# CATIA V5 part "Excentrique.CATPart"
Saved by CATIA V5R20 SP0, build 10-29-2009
Part number: Excentrique
Publications: "Plan.1", "Arête"
Bounding box of the stored display mesh (mm): x -10 to 10, y 114.981 to 189.981, z 26.94 to 101.92
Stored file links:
  C:\Users\thinkmotion1\Desktop\Khaled_IAO_Pack2\IAO_2010_1412_jclement\Non_Optimise\Excentrique.CATPart
  C:\Users\thinkmotion1\Desktop\Khaled_IAO_Pack2\IAO_2010_1412_jclement\Non_Optimise\Synthese IAO_2.CATProduct
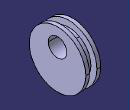
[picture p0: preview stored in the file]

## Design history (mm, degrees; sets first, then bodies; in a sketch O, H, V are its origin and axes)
Set1
  DatumCurve1 to DatumCurve3: linked copy from another document
Set2
  Plane1: type Offset, RefPlane zx-plane, Offset 152.5
Body1 (main body)
  Sketch1 on yz-plane, origin (0, 0, 0), H (0, 1, 0), V (0, 0, 1)
    circle A1 centre (152.4813, 64.4302) radius 37.5
    point P1 (152.4813, 64.4302)
    reference projected arc E1 centre (152.4813, 64.4302) radius 37.5 from (184.557, 83.8568) to (181.554, 88.1161) ccw from edge of DatumCurve1
    circle A2 centre (152.4813, 78.4302) radius 12.2498
    point P2 (152.4813, 78.4302)
    radius A2 = 12.2498
    distance P2 P1 = 14
    distance P2 P1 H = 0
    coincidence: E1 A1
  Pad1: profile Sketch1, direction (1, 0, 0), length 10, mirrored extent
  Sketch2 on Plane1, origin (0, 152.5, 0), H (-1, 0, 0), V (0, 0, 1)
    axis line L1 (-21.2821, 64.4302) -> (42.9523, 64.4302)
    reference projected line E1 through (0, 64.4302) direction (-1, 0) from axis of face of Pad1 from Sketch1.A1
    line L2 (-5, 102.0302) -> (5, 102.0302)
    line L3 (5, 102.0302) -> (5, 93.8302)
    line L4 (5, 93.8302) -> (-5, 93.8302)
    line L5 (-5, 93.8302) -> (-5, 102.0302)
    reference projected line E2 (-5, 83.8359) -> (-5, 89.8146) from edge of DatumCurve3
    length L2 = 10
    length L3 = 8.2
    distance L2 L1 = 37.6
    horizontal: L1 H, L2 H, L4 H
    coincidence: L1 E1, E2 L5
    vertical: L3 V, L5 V
  Groove1: profile Sketch2, axis Sketch2.L1, angle 360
